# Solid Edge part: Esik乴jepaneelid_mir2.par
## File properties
Author: Türk
Template: Iso Part.par
Last saved by: Türk
Revision: 2
Application: Solid Edge
Accuracy: 0,990
Username: Türk
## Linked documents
ljepaneelid.par
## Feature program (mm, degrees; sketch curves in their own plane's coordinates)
part copy "CopiedPart_1"
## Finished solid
Body 1: solid body, 86 faces, 226 edges, 140 vertices.
  Faces by surface: plane 23, spline 19, blend 12, cylinder 12, offset 9, swept 9, cone 1, sphere 1
  Edges by curve: intersection 97, line 56, curve on surface 32, circle 25, spline 16
Bounding box of the edges (mm; curved faces can reach further): 897.286 x 1810.174 x 623.521, from (-897.2775, -960.1735, -151.3958) to (0.0086, 850, 472.1255).
Cylindrical faces by radius (mm): R46.25 x1, R56.25 x1, R60 x1, R70 x1, R90 x3, R100 x1, R101 x2, R300 x1, R303.2534 x1
Conical faces (half-angle, radius in mm at the cone's reference point): 15 deg R100 x1
Spherical faces by radius (mm): R45 x1
Planar faces by outward normal: +x 4, +y 4, +z 1, -y 5, -z 3, oblique 6
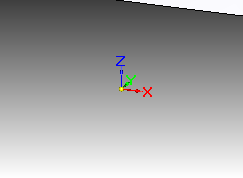
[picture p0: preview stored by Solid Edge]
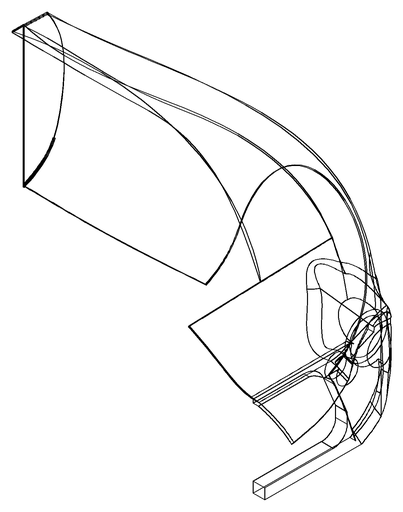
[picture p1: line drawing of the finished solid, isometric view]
